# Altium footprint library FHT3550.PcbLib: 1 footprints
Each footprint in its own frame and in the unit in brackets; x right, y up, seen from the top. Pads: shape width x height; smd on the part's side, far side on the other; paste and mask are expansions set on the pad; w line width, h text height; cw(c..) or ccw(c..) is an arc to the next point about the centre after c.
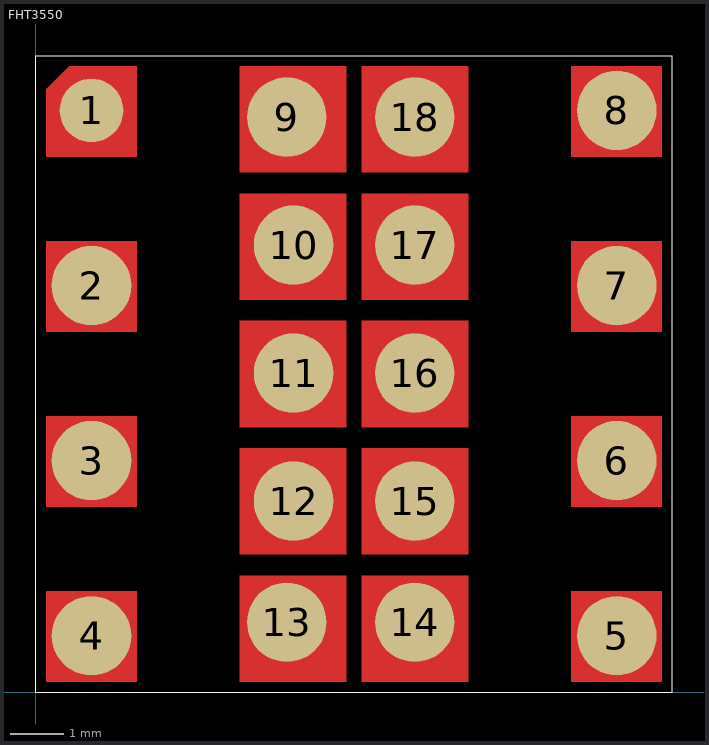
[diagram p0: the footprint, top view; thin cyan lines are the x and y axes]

## FHT3550 [mm]
pads (18):
  round 1.2 smd: 1(1.05,10.97)
  round 1.5 smd: 2(1.05,7.668) 3(1.05,4.366) 4(1.05,1.064)
  round 1.5 smd mask+0: 5(10.956,1.064) 6(10.956,4.366) 7(10.956,7.668) 8(10.956,10.97) 9(4.733,10.843) 10(4.86,8.43) 11(4.86,6.017) 12(4.86,3.604) 13(4.733,1.318) 14(7.146,1.318) 15(7.146,3.604) 16(7.146,6.017) 17(7.146,8.43) 18(7.146,10.843)
Top Layer:
  region: 0.2,6.8 1.9,6.8 1.9,8.5 0.2,8.5
  region: 6.15,0.2 8.15,0.2 8.15,2.2 6.15,2.2
  region: 3.85,0.2 5.85,0.2 5.85,2.2 3.85,2.2
  region: 6.15,2.6 8.15,2.6 8.15,4.6 6.15,4.6
  region: 3.85,2.6 5.85,2.6 5.85,4.6 3.85,4.6
  region: 6.15,5 8.15,5 8.15,7 6.15,7
  region: 3.85,5 5.85,5 5.85,7 3.85,7
  region: 6.15,7.4 8.15,7.4 8.15,9.4 6.15,9.4
  region: 3.85,7.4 5.85,7.4 5.85,9.4 3.85,9.4
  region: 3.85,9.8 5.85,9.8 5.85,11.8 3.85,11.8
  region: 6.15,9.8 8.15,9.8 8.15,11.8 6.15,11.8
  region: 10.1,10.1 11.8,10.1 11.8,11.8 10.1,11.8
  region: 10.1,6.8 11.8,6.8 11.8,8.5 10.1,8.5
  region: 10.1,3.5 11.8,3.5 11.8,5.2 10.1,5.2
  region: 10.1,0.2 11.8,0.2 11.8,1.9 10.1,1.9
  region: 0.2,0.2 1.9,0.2 1.9,1.9 0.2,1.9
  region: 0.2,3.5 1.9,3.5 1.9,5.2 0.2,5.2
  region: 0.2,10.1 0.2,11.37 0.63,11.8 1.9,11.8 1.9,10.1
Top Overlay:
  lines w0.02: 0,0 12,0 12,12 0,12 0,0
Top Paste:
  region: 0.2,10.1 0.2,11.37 0.63,11.8 1.9,11.8 1.9,10.1
  region: 0.2,6.8 1.9,6.8 1.9,8.5 0.2,8.5
  region: 0.2,3.5 1.9,3.5 1.9,5.2 0.2,5.2
  region: 0.2,0.2 1.9,0.2 1.9,1.9 0.2,1.9
  region: 10.1,0.2 11.8,0.2 11.8,1.9 10.1,1.9
  region: 10.1,3.5 11.8,3.5 11.8,5.2 10.1,5.2
  region: 10.1,6.8 11.8,6.8 11.8,8.5 10.1,8.5
  region: 10.1,10.1 11.8,10.1 11.8,11.8 10.1,11.8
  region: 6.15,9.8 8.15,9.8 8.15,11.8 6.15,11.8
  region: 3.85,9.8 5.85,9.8 5.85,11.8 3.85,11.8
  region: 3.85,7.4 5.85,7.4 5.85,9.4 3.85,9.4
  region: 6.15,7.4 8.15,7.4 8.15,9.4 6.15,9.4
  region: 3.85,5 5.85,5 5.85,7 3.85,7
  region: 6.15,5 8.15,5 8.15,7 6.15,7
  region: 3.85,2.6 5.85,2.6 5.85,4.6 3.85,4.6
  region: 6.15,2.6 8.15,2.6 8.15,4.6 6.15,4.6
  region: 3.85,0.2 5.85,0.2 5.85,2.2 3.85,2.2
  region: 6.15,0.2 8.15,0.2 8.15,2.2 6.15,2.2
Top Solder:
  region: 0.2,10.1 0.2,11.37 0.63,11.8 1.9,11.8 1.9,10.1
  region: 0.2,6.8 1.9,6.8 1.9,8.5 0.2,8.5
  region: 0.2,3.5 1.9,3.5 1.9,5.2 0.2,5.2
  region: 0.2,0.2 1.9,0.2 1.9,1.9 0.2,1.9
  region: 10.1,0.2 11.8,0.2 11.8,1.9 10.1,1.9
  region: 10.1,3.5 11.8,3.5 11.8,5.2 10.1,5.2
  region: 10.1,6.8 11.8,6.8 11.8,8.5 10.1,8.5
  region: 10.1,10.1 11.8,10.1 11.8,11.8 10.1,11.8
  region: 6.15,9.8 8.15,9.8 8.15,11.8 6.15,11.8
  region: 3.85,9.8 5.85,9.8 5.85,11.8 3.85,11.8
  region: 3.85,7.4 5.85,7.4 5.85,9.4 3.85,9.4
  region: 6.15,7.4 8.15,7.4 8.15,9.4 6.15,9.4
  region: 3.85,5 5.85,5 5.85,7 3.85,7
  region: 6.15,5 8.15,5 8.15,7 6.15,7
  region: 3.85,2.6 5.85,2.6 5.85,4.6 3.85,4.6
  region: 6.15,2.6 8.15,2.6 8.15,4.6 6.15,4.6
  region: 3.85,0.2 5.85,0.2 5.85,2.2 3.85,2.2
  region: 6.15,0.2 8.15,0.2 8.15,2.2 6.15,2.2
3D body: height 4.32, standoff 0, extent 0,0 12,12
